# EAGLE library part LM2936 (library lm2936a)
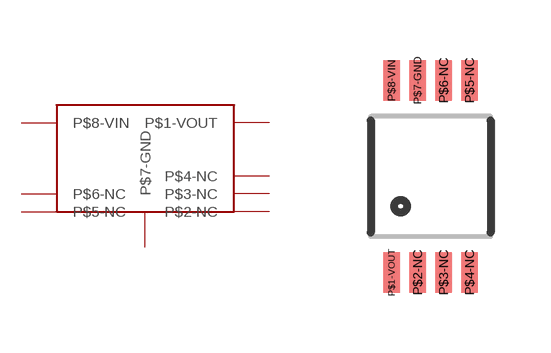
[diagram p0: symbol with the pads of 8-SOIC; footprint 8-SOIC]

Designator prefix -

## LM2936  [8-SOIC]
P$1-VOUT  P$1-VOUT  sup
P$2-NC  P$2-NC  nc
P$3-NC  P$3-NC  nc
P$4-NC  P$4-NC  nc
P$5-NC  P$5-NC  nc
P$6-NC  P$6-NC  nc
P$7-GND  P$7-GND
P$8-VIN  P$8-VIN  in

## Footprint 8-SOIC (pad centres in mm)
smd 0.41 x 1.02: P$1-VOUT -0.975,-2.4; P$2-NC -0.325,-2.4; P$3-NC 0.325,-2.4; P$4-NC 0.975,-2.4; P$5-NC 0.975,2.4; P$6-NC 0.325,2.4; P$7-GND -0.325,2.4; P$8-VIN -0.975,2.4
